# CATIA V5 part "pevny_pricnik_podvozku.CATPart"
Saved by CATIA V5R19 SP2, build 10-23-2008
Part number: pevný příčník podvozku
Bounding box of the stored display mesh (mm): x -30 to 1210, y -1565 to 1565, z -174.984 to 1660
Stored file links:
  C:\Users\Martiin\Desktop\9.semestr\Projekt-diplomka\3D model\pevny_pricnik_podvozku.CATPart
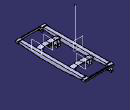
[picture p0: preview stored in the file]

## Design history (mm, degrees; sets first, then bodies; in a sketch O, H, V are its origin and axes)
Body1 (main body)
  Sketch1 on yz-plane, origin (0, 0, 0), H (0, 1, 0), V (0, 0, 1)
    construction line L1 (0, 0) -> (0, 143.6319)
    point P1 (0, 143.6319)
    line L2 (0, 160) -> (-1350, 160)
    point P2 (0, 160)
    point P3 (-1350, 160)
    line L3 (-1350, 160) -> (-1350, 74.3654)
    point P4 (-1350, 74.3654)
    line L4 (-1350, 74.3654) -> (-500, 0)
    point P5 (-500, 0)
    line L5 (-500, 0) -> (0, 0)
    point P6 (0, 143.6319)
    point P7 (0, 160)
    point P8 (0, 0)
    point P9 (500, 0)
    line L6 (500, 0) -> (0, 0)
    point P10 (1350, 74.3654)
    line L7 (1350, 74.3654) -> (500, 0)
    point P11 (1350, 160)
    line L8 (1350, 160) -> (1350, 74.3654)
    line L9 (0, 160) -> (1350, 160)
    distance L3 L1 = 1350
    distance P5 L1 = 500
    distance L5 L2 = 160
    angle L4 L5 = 175
    vertical: L1 V, L3 V
    coincidence: P2 L1, P5 H, O P8, P2 P7
    horizontal: L2 H, L5 H
    symmetry: P1 P6 L1, P2 P7 L1, O P8 L1, P5 P9 L1, L5 L6 L1, P4 P10 L1, L4 L7 L1, P3 P11 L1, L3 L8 L1, L2 L9 L1
  Pad1: profile Sketch1, direction (1, 0, 0), length 140
  Shell1: IntOffset 10, Face face of Pad1 from Sketch1.L9, ExtOffset 0
  Sketch2 on face of Shell1, origin (0, -1340, 0), H (-1, 0, 0), V (0, 0, 1)
    line L1 (-130, 160) -> (-10, 160)
    line L2 (-10, 160) -> (-10, 150)
    line L3 (-10, 150) -> (-130, 150)
    line L4 (-130, 150) -> (-130, 160)
    reference projected line E1 (-10, 160) -> (-130, 160) from edge [face of Pad1 from Sketch1.L2 | face of Shell1]
    reference projected line E2 (-130, 160) -> (-130, 83.5287) from edge [face of Shell1 | face of Shell1]
    reference projected line E3 (-10, 160) -> (-10, 83.5287) from edge [face of Shell1 | face of Shell1]
    distance L3 L1 = 10
    horizontal: L1 H, L3 H
    vertical: L2 V, L4 V
    coincidence: L1 E1, L4 E2, E3 L2
  Pad2: profile Sketch2, direction (0, 1, 0), up to the existing solid (limit type 2)
  Plane1: type Offset, RefPlane face of Pad1 from Sketch1.L3, Offset 550
  Sketch3 on Plane1, origin (0, -800, 0), H (-1, 0, 0), V (0, 0, 1)
    line L1 (-366.8513, 160) -> (-590, 160)
    point P1 (-590, 160)
    point P2 (-590, 140)
    line L2 (-590, 140) -> (-368.601, 140)
    point P3 (-368.601, 140)
    line L3 (-368.601, 140) -> (-140, 99.6915)
    reference projected line E1 (0, 160) -> (-140, 160) from edge [face of Pad1 from Sketch1.L3 | face of Pad1 from Sketch1.L2]
    line L4 (-366.8513, 160) -> (-140, 120)
    point P4 (-366.8513, 160)
    line L5 (-140, 120) -> (-140, 99.6915)
    point P5 (-140, 120)
    point P6 (-140, 99.6915)
    reference projected line E2 (-140, 160) -> (-140, 74.3654) from edge [face of Pad1 from Sketch1.L3 | end face of Pad1]
    construction line L6 (-590, 160) -> (-590, -11.9154)
    point P8 (-590, 160)
    point P9 (-813.1487, 160)
    line L7 (-813.1487, 160) -> (-590, 160)
    point P10 (-811.399, 140)
    point P11 (-590, 140)
    line L8 (-590, 140) -> (-811.399, 140)
    point P12 (-1040, 99.6915)
    line L9 (-811.399, 140) -> (-1040, 99.6915)
    point P13 (-1040, 120)
    line L10 (-813.1487, 160) -> (-1040, 120)
    line L11 (-1040, 120) -> (-1040, 99.6915)
    distance L2 L1 = 20
    distance L3 L4 = 20
    angle L1 L4 = 170
    distance P5 L1 = 40
    distance P2 L5 = 450
    horizontal: L1 H, L2 H
    coincidence: E1 L1, E2 L5, P1 P8, P2 P11
    vertical: L5 V, L6 V
    symmetry: P1 P8 L6, P4 P9 L6, L1 L7 L6, P3 P10 L6, P2 P11 L6, L2 L8 L6, P6 P12 L6, L3 L9 L6, P5 P13 L6, L4 L10 L6, L5 L11 L6
  Pad3: profile Sketch3, direction (0, 1, 0), length 190
  Plane2: type Offset, RefPlane face of Pad1 from Sketch1.L3, Offset 1350
  Mirror1: of Pad3, about Plane2
  Plane3: type 2Lines, Element1 edge [face of Pad3 from Sketch3.L7 | face of Pad3 from Sketch3.L1], Element2 edge [face of Pad3 from Sketch3.L2 | face of Pad3 from Sketch3.L8]
  Mirror2: of Pad1, about Plane3
  Shell2: IntOffset 10, Face face of Mirror2, ExtOffset 0
  Mirror3: of Pad2, about Plane3
  Plane4: type Offset, RefPlane face of Mirror2, Offset 55, reversed
  Sketch4 on Plane4, origin (985, 0, 0), H (0, 1, 0), V (0, 0, 1)
    point P1 (610, 60)
    line L1 (610, 60) -> (590.9881, -47.8217)
    line L2 (772.4683, 60) -> (748.5574, -75.6054)
    reference projected line E1 (610, 98.7164) -> (610, 140) from edge [face of Mirror1 | face of Mirror1]
    line L3 (610, 60) -> (772.4683, 60)
    point P3 (610, 60)
    construction line L4 (709.1227, 161.4509) -> (616.3703, -364.5737)
    construction line L5 (579.7268, -111.6877) -> (721.5262, -136.6907)
    point P6 (579.7268, -111.6877)
    arc A1 centre (664.7851, -90) radius 85 from (590.9881, -47.8217) to (748.5574, -75.6054) ccw
    point P8 (664.7851, -90)
    reference projected line E2 (1350, 160) -> (0, 160) from edge [face of Pad1 from Sketch1.L9 | end face of Pad1]
    reference projected line E3 (1350, 160) -> (0, 160) from edge [face of Pad1 from Sketch1.L9 | end face of Pad1]
    circle A2 centre (664.7851, -90) radius 35
    angle L3 L2 = 80
    distance L1 L2 = 160
    distance L4 L1 = 80
    radius A1 = 85
    distance L3 E2 = 100
    distance P8 E3 = 250
    radius A2 = 35
    coincidence: P1 E1, P3 L1, P1 L3, P6 L1, P8 L4, P1 P3
    horizontal: L3 H
    perpendicularity: L5 L2
  Pad4: profile Sketch4, direction (1, 0, 0), length 15
  Pad5: profile face of Pad4 from Sketch4.L3, direction along edge [start face of Pad4 | face of Pad4 from Sketch4.L2], up to face of Mirror1
  RectPattern1: of Pad4, direction 1 instances 2, spacing 105, along edge [face of Mirror1 | face of Mirror1]
  Pad6: profile face of RectPattern1, direction along edge [face of Pad6 | face of RectPattern1], up to the existing solid (limit type 2)
  Plane5: type 2Lines, Element1 edge [face of Mirror1 | face of Mirror1], Element2 edge [face of Mirror1 | face of Mirror1]
  Mirror4: of Pad4, about Plane5
  Mirror5: of the body so far, about Plane5
  Mirror6: of Pad4, about Plane2
  Mirror7: of the body so far, about Plane2
  Sketch5 on face of Mirror7, origin (0, 0, 140), H (1, 0, 0), V (0, -1, 0)
    point P1 (502.5, 660)
    line L1 (502.5, 660) -> (542.5, 660)
    line L2 (542.5, 660) -> (542.5, 610)
    line L3 (542.5, 610) -> (502.5, 610)
    line L4 (502.5, 610) -> (502.5, 660)
    point P2 (542.5, 660)
    point P3 (542.5, 610)
    point P4 (502.5, 610)
    reference projected line E1 (590, 610) -> (368.601, 610) from edge [face of Mirror7 | face of Mirror7]
    reference projected line E2 (590, 800) -> (590, 610) from edge [face of Mirror7 | face of Mirror7]
    point P7 (637.5, 660)
    point P8 (677.5, 660)
    line L5 (677.5, 660) -> (637.5, 660)
    point P9 (677.5, 610)
    line L6 (677.5, 610) -> (677.5, 660)
    point P10 (637.5, 610)
    line L7 (637.5, 610) -> (677.5, 610)
    line L8 (637.5, 660) -> (637.5, 610)
    construction line L9 (522.5, 743.471) -> (522.5, 588.3346)
    distance L1 L3 = 50
    distance L4 L2 = 40
    distance L9 E2 = 67.5
    distance L9 L2 = 20
    horizontal: L1 H, L3 H
    vertical: L2 V, L4 V, L9 V
    coincidence: L3 E1
    symmetry: P2 P7 E2, P1 P8 E2, L1 L5 E2, P4 P9 E2, L4 L6 E2, P3 P10 E2, L3 L7 E2, L2 L8 E2
  Pad7: profile Sketch5, direction (0, 0, -1), length 100
  Sketch6 on end face of Pad7, origin (522.8217, -674.2765, 40), H (1, 0, 0), V (0, -1, 0)
    point P1 (-0.3217, -39.2765)
    reference projected line E1 (19.6783, -64.2765) -> (19.6783, 35.7235) from edge [face of Pad7 from Sketch5.L2 | end face of Pad7]
    reference projected line E2 (24.6783, -14.2765) -> (-25.3217, -14.2765) from edge [face of Pad7 from Sketch5.L1 | end face of Pad7]
    distance P1 E1 = 20
    distance P1 E2 = 25
  Hole1: placed by Sketch6, at (522.5, -635, 40) direction (0, 0, 1), diameter 21, depth 22
  RectPattern2: of Hole1, direction 1 instances 2, spacing 135, along edge [face of Pad7 from Sketch5.L1 | end face of Pad7] reversed
  Mirror8: of the body so far, about Plane2
  Plane6: type Offset, RefPlane face of Mirror8, Offset 30, reversed
  Sketch7 on Plane6, origin (1210, 0, 0), H (0, -1, 0), V (0, 0, 1)
    line L1 (1350, 167) -> (1350, 67)
    line L2 (1350, 67) -> (1360, 67)
    line L3 (1360, 67) -> (1360, 82)
    line L4 (1360, 82) -> (1463.2198, 82)
    line L5 (1470, 122) -> (1470, 152)
    line L6 (1470, 152) -> (1360, 152)
    line L7 (1360, 152) -> (1360, 167)
    line L8 (1360, 167) -> (1350, 167)
    reference projected line E1 (-1350, 160) -> (1350, 160) from edge [face of Mirror8 | face of Mirror8]
    reference projected line E2 (1350, 160) -> (1350, 74.3654) from edge [face of Mirror8 | face of Mirror8]
    point P8 (1463.2198, 82)
    line L9 (1463.2198, 82) -> (1470.8803, 75.5721)
    line L10 (1470.8803, 75.5721) -> (1493.3778, 102.3837)
    line L11 (1493.3778, 102.3837) -> (1470, 122)
    point P11 (1470, 122)
    distance L6 E1 = 8
    distance L4 L6 = 70
    distance L7 L1 = 10
    distance L8 L6 = 15
    distance L2 L4 = 15
    distance L5 L1 = 120
    distance L10 P8 = 10
    angle L5 L11 = 130
    distance L11 L9 = 35
    distance P11 L6 = 30
    vertical: L1 V, L3 V, L5 V, L7 V
    horizontal: L2 H, L4 H, L6 H, L8 H
    coincidence: L7 L3, L1 E2
    perpendicularity: L10 L9
  Pad8: profile Sketch7, direction (-1, 0, 0), length 200
  RectPattern3: of Pad8, direction 1 instances 2, spacing 1040, along edge [face of Mirror8 | face of Mirror8] reversed
  Sketch8 on end face of Pad8, origin (1010, 0, 0), H (0, -1, 0), V (0, 0, 1)
    line L1 (1493.3778, 102.3837) -> (1470, 122)
    line L2 (1470, 122) -> (1470, 152)
    line L3 (1470, 152) -> (1445, 152)
    line L4 (1445, 152) -> (1445, 82)
    line L5 (1445, 82) -> (1463.2198, 82)
    line L6 (1463.2198, 82) -> (1470.8803, 75.5721)
    line L7 (1470.8803, 75.5721) -> (1493.3778, 102.3837)
    reference projected line E1 (1493.3778, 102.3837) -> (1470, 122) from edge [face of RectPattern3 | face of RectPattern3]
    reference projected line E2 (1470.8803, 75.5721) -> (1493.3778, 102.3837) from edge [face of RectPattern3 | face of RectPattern3]
    reference projected line E3 (1463.2198, 82) -> (1470.8803, 75.5721) from edge [face of RectPattern3 | face of RectPattern3]
    reference projected line E4 (1360, 82) -> (1463.2198, 82) from edge [face of RectPattern3 | face of RectPattern3]
    reference projected line E5 (1470, 152) -> (1360, 152) from edge [face of RectPattern3 | face of RectPattern3]
    reference projected line E6 (1470, 122) -> (1470, 152) from edge [face of RectPattern3 | face of RectPattern3]
    distance L2 L4 = 25
    vertical: L2 V, L4 V
    horizontal: L3 H, L5 H
    parallelism: L6 L1
    perpendicularity: L7 L1
    coincidence: E1 L1, L7 E2, L6 E3, L5 E4, L3 E5, L2 E6
  Pad9: profile Sketch8, direction (-1, 0, 0), up to the existing solid (limit type 2)
  Plane7: type Offset, RefPlane face of RectPattern3, Offset 50, reversed
  Sketch9 on Plane7, origin (0, 0, 32), H (1, 0, 0), V (0, 1, 0)
    line L1 (170, -1390) -> (90, -1390)
    line L2 (90, -1390) -> (90, -1565)
    line L3 (90, -1565) -> (170, -1565)
    line L4 (170, -1565) -> (170, -1390)
    reference projected line E1 (170, -1360) -> (-30, -1360) from edge [face of RectPattern3 | face of RectPattern3]
    reference projected line E2 (170, -1360) -> (170, -1463.2198) from edge [face of RectPattern3 | face of RectPattern3]
    distance L1 E1 = 30
    distance L3 L1 = 175
    distance L4 L2 = 80
    horizontal: L1 H, L3 H
    vertical: L2 V, L4 V
    coincidence: L4 E2
  Pad10: profile Sketch9, direction (0, 0, -1), length 20
  Sketch10 on end face of Pad10, origin (0, 0, 12), H (1, 0, 0), V (0, -1, 0)
    point P1 (90, 1565)
    line L1 (90, 1565) -> (170, 1565)
    line L2 (170, 1565) -> (170, 1525)
    line L3 (170, 1525) -> (90, 1525)
    line L4 (90, 1525) -> (90, 1565)
    point P2 (170, 1565)
    point P3 (170, 1525)
    point P4 (90, 1525)
    construction line L5 (80.7783, 1477.5) -> (208.9645, 1477.5)
    construction line L6 (62.8179, 1545) -> (221.1409, 1545)
    reference projected line E1 (170, 1498.0309) -> (170, 1390) from edge [end face of Pad10 | face of Pad10 from Sketch9.L4]
    reference projected line E2 (90, 1390) -> (90, 1498.0309) from edge [end face of Pad10 | face of Pad10 from Sketch9.L2]
    reference projected line E3 (90, 1565) -> (170, 1565) from edge [end face of Pad10 | face of Pad10 from Sketch9.L3]
    point P9 (90, 1430)
    point P10 (170, 1430)
    line L7 (170, 1430) -> (90, 1430)
    point P11 (90, 1390)
    line L8 (90, 1430) -> (90, 1390)
    point P12 (170, 1390)
    line L9 (90, 1390) -> (170, 1390)
    line L10 (170, 1390) -> (170, 1430)
    distance L6 L5 = 67.5
    distance L3 L6 = 20
    distance L3 L1 = 40
    horizontal: L1 H, L3 H, L5 H, L6 H
    vertical: L2 V, L4 V
    coincidence: E1 L2, E2 L4, L1 E3
    symmetry: P4 P9 L5, P3 P10 L5, L3 L7 L5, P1 P11 L5, L4 L8 L5, P2 P12 L5, L1 L9 L5, L2 L10 L5
  Pad11: profile Sketch10, direction (0, 0, -1), length 50
  Sketch11 on face of Pad11, origin (90, 0, 0), H (0, -1, 0), V (0, 0, 1)
    point P1 (1565, 32)
    line L1 (1565, 32) -> (1493.3778, 102.3837)
    point P2 (1493.3778, 102.3837)
    line L2 (1493.3778, 102.3837) -> (1470.8803, 75.5721)
    line L3 (1470.8803, 75.5721) -> (1463.2198, 82)
    line L4 (1463.2198, 82) -> (1419.1631, 82)
    line L5 (1419.1631, 82) -> (1390.3646, 32)
    line L6 (1390.3646, 32) -> (1565, 32)
    reference projected line E1 (1390, 32) -> (1565, 32) from edge [face of Pad11 | start face of Pad10]
    reference projected line E2 (1470.8803, 75.5721) -> (1493.3778, 102.3837) from edge [face of RectPattern3 | face of RectPattern3]
    reference projected line E3 (1360, 82) -> (1463.2198, 82) from edge [face of RectPattern3 | face of RectPattern3]
    reference projected line E4 (1463.2198, 82) -> (1470.8803, 75.5721) from edge [face of RectPattern3 | face of RectPattern3]
    reference projected line E5 (1493.3778, 102.3837) -> (1470, 122) from edge [face of Pad9 | face of RectPattern3]
    reference projected point E6 (1565, 32) from vertex [face of Pad11 | face of Pad11 | start face of Pad10]
    horizontal: L4 H
    coincidence: L6 E1, L2 E2, L4 E3, L3 E4, P2 E5, P1 E6
  Pad12: profile Sketch11, direction (1, 0, 0), length 80
  Sketch12 on end face of Pad11, origin (137.7668, -1406.1166, -38), H (1, 0, 0), V (0, -1, 0)
    point P1 (-7.7668, 3.8834)
    reference projected line E1 (-47.7668, -16.1166) -> (32.2332, -16.1166) from edge [face of Pad11 | end face of Pad11]
    reference projected line E2 (32.2332, 23.8834) -> (32.2332, -16.1166) from edge [face of Pad12 | end face of Pad11]
    distance P1 E1 = 20
    distance P1 E2 = 40
  Hole2: placed by Sketch12, at (130, -1410, -38) direction (0, 0, 1), diameter 21, depth 22
  Mirror9: of Pad8, Pad9, Pad10, Pad11, Pad12, Hole2, about Plane2
  Mirror10: of Pad9, about Plane2
  Mirror11: of the body so far, about Plane2
  RectPattern4: of Hole2, direction 1 instances 2, spacing 135, along edge [face of Mirror11 | face of Mirror11]
  Sketch13 on face of Mirror11, origin (144.1176, 1544.9664, -38), H (1, 0, 0), V (0, -1, 0)
    point P1 (-14.1176, -0.0336)
    reference projected line E1 (25.8824, 114.9664) -> (25.8824, 154.9664) from edge [face of Mirror11 | face of Mirror9]
    reference projected line E3 (-54.1176, 19.9664) -> (25.8824, 19.9664) from edge [face of Mirror11 | face of Mirror11]
    distance P1 E1 = 40
    distance P1 E3 = 20
  Hole3: placed by Sketch13, at (130, 1545, -38) direction (0, 0, 1), diameter 21, depth 22
  Point1: type Between, FirstPoint {point type OnCurve, Support edge [face of Mirror11 | face of Mirror11], Ratio 0.5}, SecondPoint {point type OnCurve, Support edge [face of Mirror11 | face of Mirror11], Ratio 0.5}, Ratio 0
  Line1: type Normal, RefPoint Point1, RefSkin face of Mirror11, Start 0, End 1500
